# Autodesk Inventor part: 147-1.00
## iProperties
Created: 2007-06
Part Number: 147-1.00
Document SubType Name: Modeling
Designer: btaylor
Density: 1 g/cm^3
Author: btaylor
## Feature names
1. Extrusion1
2. Extrusion2
3. Fillet1
4. Fillet2
5. Chamfer1
6. Chamfer2
7. Extrusion3
8. Fillet3
9. Fillet4
